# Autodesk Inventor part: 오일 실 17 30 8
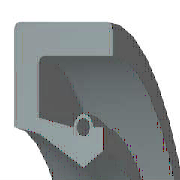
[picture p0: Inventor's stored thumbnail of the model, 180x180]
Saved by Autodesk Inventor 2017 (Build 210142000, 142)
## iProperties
IsCustomPart: 1
Created: 2012-02
Part Number: 오일 실 17 30 8
Material: 고무
Description: 오일-실
Document SubType Name: Modeling
Standard: KS B 2804
Designer: test
Standards Organization: KS
Language: ko-KR
Size Designation: S - 17 32 8
Categories: <MemberInstance><Categories><Category DisplayName="샤프트 부품" InternalName="7f7aeb1f-a693-4053-b835-cee3144e0d98" Mnemonic="SHFT"><Category DisplayName="실링" Intern
Density: 0.93 g/cm^3
Appearance: 고무 - 검은색 - 버전 1.1
Author: test
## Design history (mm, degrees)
revolve "본체" stored, may be unused: angle "d17" = 90 deg
revolve "스프링1" stored, may be unused: angle "d18" = 90 deg
body "Solid1"
sketch "스케치1"
  geometry: L1 (0, 15)-(8, 15); L2 (8, 15)-(8, 13.75); L3 (8, 13.75)-(1.75, 13.75); L4 (0, 15)-(0, 10.6); L5 (0, 10.6)-(1.75, 10.25); L6 (1.75, 10.25)-(4.9, 8.5); L7 (4.9, 8.5)-(0, 8.5); L8 (6.3, 9.375)-(6.3, 10.6); L9 (0, 0)-(9.586, 0) reference; L10 (4.9, 8.5)-(6.3, 9.375); L11 (0, 19.2)-(0, -3.2) reference; L12 (-1.917, 0)-(11.503, 0) reference; L13 (4.2, 10.6)-(1.75, 11.09); L14 (1.75, 11.09)-(1.75, 13.75); L15 (6.3, 10.6)-(5.6, 10.6); C1 r 0.455 at (4.9, 10.6); A1 r 0.7 centre (4.9, 10.6) between (5.6, 10.6) and (4.2, 10.6)
  constraints: 26 end point, 5 horizontal alignment, 4 perpendicular, 2 centre point, 2 collinear, 2 horizontal, 2 parallel, 2 point on circle, 2 point on line, 2 vertical alignment, 1 coincident
  dimensions: "d0" = 30 diameter of L1 L9 (= SD2); "d1" = 18.75 diameter of L8.start L9 (= ABDM); "d2" = 1.25 distance of L1.end L2.end (computed from SD); "d3" = 0.91 diameter of C1 (= SPDI); "d4" = 1.4 diameter of A1 (= SPDA); "d5" = 17 diameter of L6.end L9 (= NND); "d6" = 20.5 diameter of L5.end L9 (= TKDM); "d7" = 21.2 diameter of L4.end L9 (= HLDM); "d8" = 4.9 distance from line of C1.centre L4 (= SPDST); "d9" = 6.3 distance between parallel lines of L8 L4 (= SDI); "d10" = 8 distance between parallel lines of L2 L4 (= SWDT); "d12" = 1.75 distance between parallel lines of L14 L4 (= SD)
fillet "모깎기1" dims "d11" = 0.3 (= RR)
other parameters: "SD2" = 30 [user parameter; used in 1 equation term], "SWDT" = 8 [user parameter; used in 1 equation term], "RR" = 0.3 [user parameter; used in 1 equation term], "SD" = 1.75 [user parameter; used in 2 equation terms], "NND" = 17 [user parameter; used in 1 equation term], "SPDA" = 1.4 [user parameter; used in 1 equation term], "SPDI" = 0.91 [user parameter; used in 1 equation term], "TKDM" = 20.5 [user parameter; used in 1 equation term], "HLDM" = 21.2 [user parameter; used in 1 equation term], "ABDM" = 18.75 [user parameter; used in 1 equation term], "SDI" = 6.3 [user parameter; used in 1 equation term], "SPDST" = 4.9 [user parameter; used in 1 equation term], "d13" = 0, "d14" = 0, "d15" = 0, "LAB" = 0.35 [user parameter]
